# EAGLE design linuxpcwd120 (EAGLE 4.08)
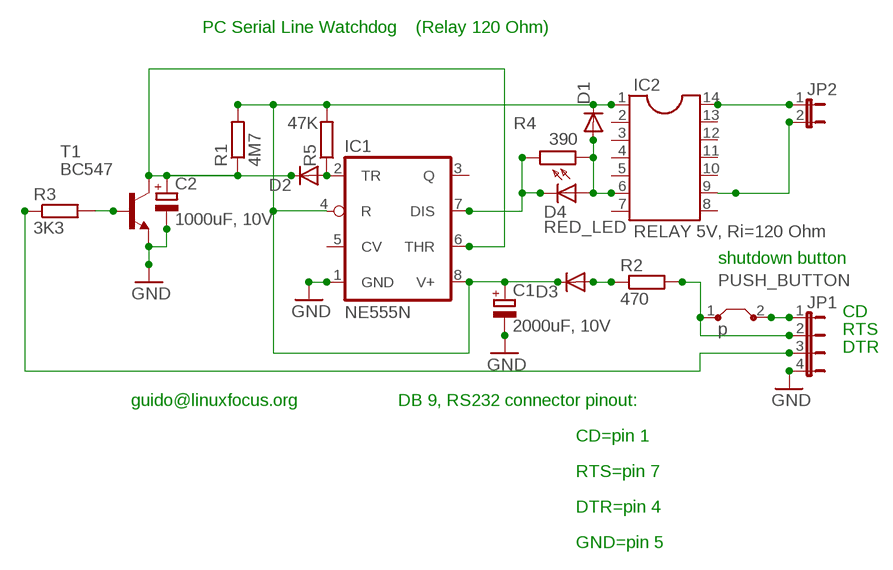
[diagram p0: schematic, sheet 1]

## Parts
C1  2000uF, 10V  CPOL-EUE3.5-10  [E3,5-10]
C2  1000uF, 10V  CPOL-EUE3.5-10  [E3,5-10]
D1  DIODE-D-5  [D-5]
D2  DIODE-D-7.5  [D-7.5]
D3  DIODE-D-5  [D-5]
D4  RED_LED  LED3MM  [LED3MM]
IC1  NE555N  [DIL08]
IC2  RELAY 5V, Ri=120 Ohm  DIL14  [DIL14]
JP1  JP4E  [JP4]
JP2  JP1E  [JP1]
PUSH_BUTTON  p  J5MM  [05]
R1  4M7  R-EU_0204/5  [0204/5]
R2  470  R-EU_0204/5  [0204/5]
R3  3K3  R-EU_0204/5  [0204/5]
R4  390  R-EU_0204/5  [0204/5]
R5  47K  R-EU_0204/7  [0204/7]
T1  BC547  [TO92]

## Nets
GND: C1.- C2.- IC1.1(GND) JP1.4 T1.1(E)
N$2: D2.A IC1.2(TR) R5.1
N$3: C2.+ D2.C IC1.6(THR) R1.1 T1.3(C)
N$5: R3.2 T1.2(B)
N$6: D3.A R2.1
N$8: IC2.14 JP2.1
N$9: D1.A D4.A IC2.6 R4.2
N$11: D4.K(C) IC1.7(DIS) R4.1
N$12: IC2.9 JP2.2
N$13: JP1.1 PUSH_BUTTON.2
N$14: JP1.2 PUSH_BUTTON.1 R2.2
N$15: JP1.3 R3.1
V+: C1.+ D1.C D3.C IC1.4(R) IC1.8(V+) IC2.1 R1.2 R5.2
Unconnected: IC1.3(Q) IC1.5(CV) IC2.2 IC2.3 IC2.4 IC2.5 IC2.7 IC2.8 IC2.10 IC2.11 IC2.12 IC2.13

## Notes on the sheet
- PC Serial Line Watchdog | (Relay 120 Ohm)
- shutdown button
- CD
- RTS
- DTR
- guido@linuxfocus.org | DB 9, RS232 connector pinout:
- CD=pin 1
- RTS=pin 7
- DTR=pin 4
- GND=pin 5

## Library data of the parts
C1 C2 = rclgus:CPOL-EU: POLARIZED CAPACITOR, European symbol
D1-D3 = diode:DIODE-: DIODE
D4 = led:LED3MM: LED
IC1 = linear:*555: TIMER
IC2 = dil:DIL14: SOCKET Dual In Line
JP1 = jumper:JP4E: JUMPER
JP2 = jumper:JP1E: JUMPER
PUSH_BUTTON = jumper:J: Bridge
R1-R5 = rclgus:R-EU_: RESISTOR, European symbol
T1 = transistor-npn:BC547: NPN TRANSISTOR

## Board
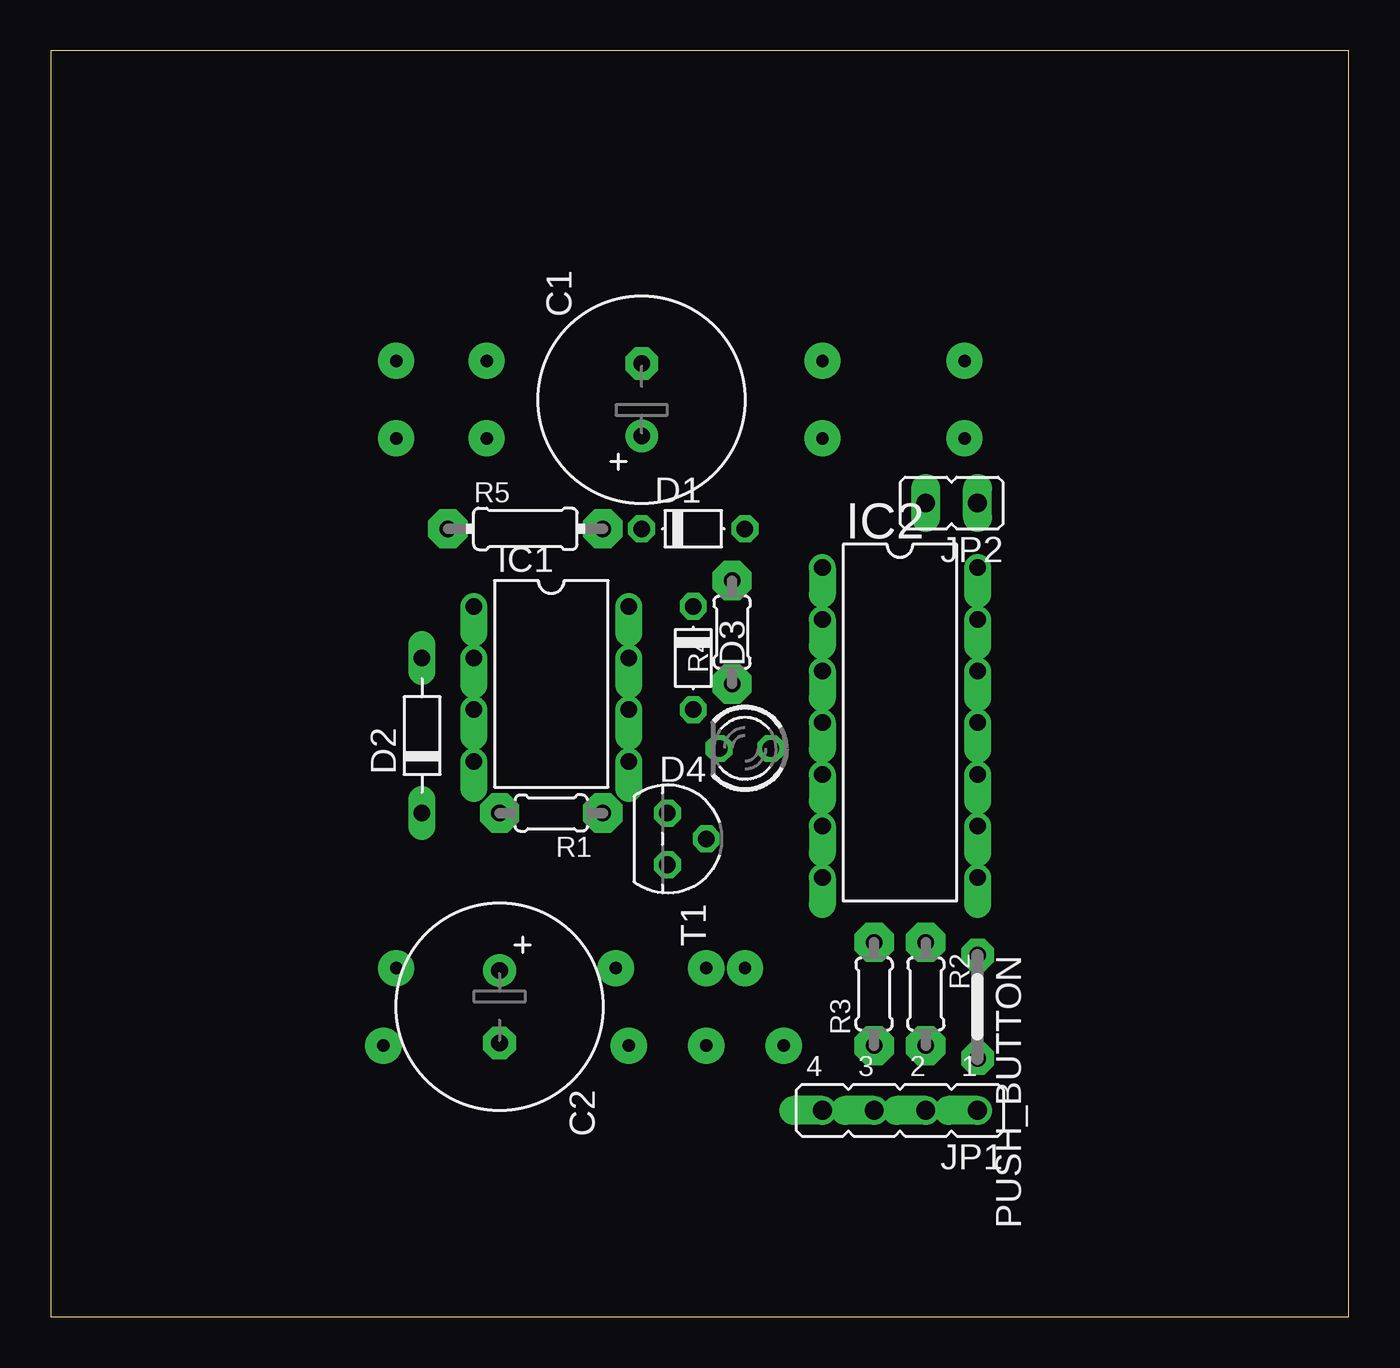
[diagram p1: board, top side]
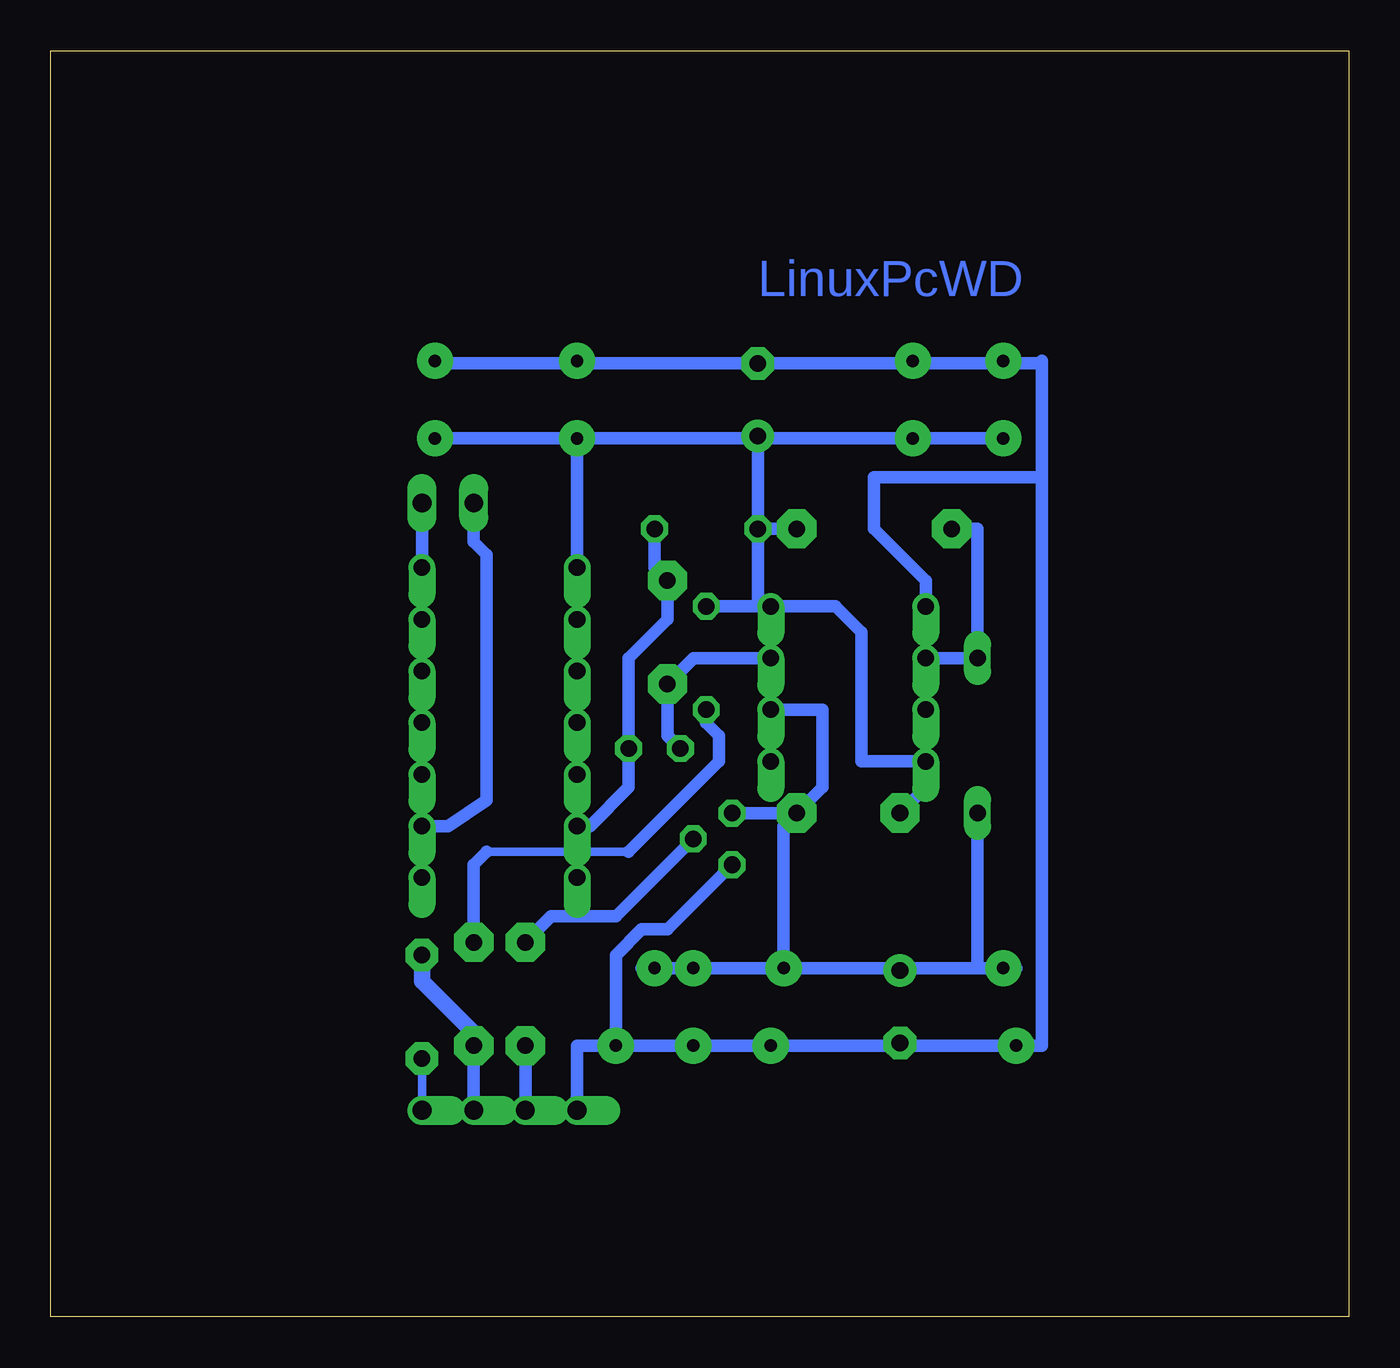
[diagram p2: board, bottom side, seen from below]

Size 63.8 x 62.22 mm. Coordinates in mm from the lower left corner, seen from the top.
Outline: 0,0 63.8,0 63.8,62.22 0,62.22 0,0
Copper layers used: Top, Bottom

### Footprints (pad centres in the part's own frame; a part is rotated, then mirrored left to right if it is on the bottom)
E3,5-10 = drill 0.813 pad 1.6 round: + -1.778,0 | drill 0.813 pad 1.6 octagon: - 1.778,0
D-5 = drill 0.813 octagon: A 2.54,0; C -2.54,0
D-7.5 = drill 0.813 long: A 3.81,0; C -3.81,0
LED3MM = drill 0.813 octagon: A -1.27,0; K 1.27,0
DIL08 = drill 0.813 offset: 1 -3.81,-3.81; 2 -1.27,-3.81; 3 1.27,-3.81; 4 3.81,-3.81; 5 3.81,3.81; 6 1.27,3.81; 7 -1.27,3.81; 8 -3.81,3.81
DIL14 = drill 0.813 offset: 1 -7.62,-3.81; 2 -5.08,-3.81; 3 -2.54,-3.81; 4 0,-3.81; 5 2.54,-3.81; 6 5.08,-3.81; 7 7.62,-3.81; 8 7.62,3.81; 9 5.08,3.81; 10 2.54,3.81; 11 0,3.81; 12 -2.54,3.81; 13 -5.08,3.81; 14 -7.62,3.81
JP4 = drill 0.914 offset: 1 -3.81,0; 2 -1.27,0; 3 1.27,0; 4 3.81,0
JP1 = drill 0.914 long: 1 0,-1.27; 2 0,1.27
05 = drill 0.813 pad 1.6 octagon: 1 -2.54,0; 2 2.54,0
0204/5 = drill 0.813 pad 1.93 octagon: 1 -2.54,0; 2 2.54,0
0204/7 = drill 0.813 pad 1.93 octagon: 1 -3.81,0; 2 3.81,0
TO92 = drill 0.813 octagon: 1 1.27,0; 2 0,1.905; 3 -1.27,0

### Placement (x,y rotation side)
C1  29.05,45.08 90 top
C2  22.06,15.23 270 top
D1  31.59,38.73 0 top
D2  18.25,28.57 90 top
D3  31.59,32.38 270 top
D4  34.12,27.94 180 top
IC1  24.6,31.11 270 top
IC2  41.75,29.2 270 top
JP1  41.75,10.16 180 top
JP2  44.29,40 90 top
PUSH_BUTTON  45.55,15.23 270 top
R1  24.6,24.76 180 top
R2  43.02,15.87 270 top
R3  40.48,15.87 90 top
R4  33.49,33.65 90 top
R5  23.33,38.73 0 top
T1  30.32,23.49 270 top

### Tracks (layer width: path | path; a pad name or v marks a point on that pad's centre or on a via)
GND  (via drill 0.61 pad 1.78)
  Bottom 0.254: 21.43,13.33 C2.- | 21.43,13.33
  Bottom 0.61: 15.2,46.86 C1.- | 15.2,46.86 15.08,46.98 15.08,41.27 | 15.08,41.27 15.08,13.33 v16.34,13.33 21.43,13.33 v28.41,13.33 v32.22,13.33 v36.03,13.33 | v36.03,13.33 37.94,13.33 JP1.4 | 15.2,46.86 44.79,46.86 v44.92,46.98 | IC1.1 20.79,36.19 23.33,38.73 23.33,41.27 15.08,41.27 | T1.1 33.49,19.04 34.76,19.04 36.03,17.77 v36.03,13.33
N$1  (via drill 0.61 pad 1.78)
  other vias: 16.98,46.98
N$2
  Bottom 0.61: IC1.2 D2.A 18.25,38.73 R5.1
N$3  (via drill 0.61 pad 1.78)
  Bottom 0.254: 21.43,17.14 C2.+ | 21.43,17.14
  Bottom 0.61: R1.1 T1.3 | IC1.6 25.87,29.84 25.87,26.03 R1.1 | 18.25,17.14 D2.C | 18.25,17.14 v16.98,17.14 16.34,17.14 | 18.25,17.14 21.43,17.14 v27.77,17.14 | v27.77,17.14 v32.22,17.14 v34.12,17.14 34.76,17.14 | v27.77,17.14 27.77,24.12 R1.1
N$4  (via drill 0.61 pad 1.78)
  other vias: 37.94,46.98
N$5
  Bottom 0.61: T1.2 36.03,19.68 39.21,19.68 R3.2
N$6
  Bottom 0.406: 35.4,22.85 42.38,22.85
  Bottom 0.61: D3.A 31.59,29.2 30.95,28.57 30.95,27.3 35.4,22.85 | 43.02,19.68 R2.1 43.02,22.22 42.38,22.85
N$7  (via drill 0.61 pad 1.78)
  other vias: 21.43,46.98
N$8
  Bottom 0.61: IC2.14 JP2.1
N$9
  Bottom 0.61: D1.A 34.12,36.83 R4.2 33.49,34.28 35.4,32.38 D4.A 35.4,26.03 37.3,24.12 IC2.6
N$11
  Bottom 0.61: D4.K 33.49,28.57 R4.1 32.22,32.38 IC1.7
N$12
  Bottom 0.61: JP2.2 43.02,38.09 42.38,37.46 42.38,25.4 44.29,24.12 IC2.9
N$13
  Bottom 0.406: JP1.1 PUSH_BUTTON.2
N$14  (via drill 0.61 pad 1.78)
  Top 0.254: R2.2
  Bottom 0.61: JP1.2 R2.2
  Bottom 0.813: R2.2 43.02,13.96 45.55,16.5 PUSH_BUTTON.1
  other vias: 43.01,13.33
N$15
  Bottom 0.61: JP1.3 R3.1
V+  (via drill 0.61 pad 1.78)
  Bottom 0.61: D1.C R5.2 | 29.05,34.92 IC1.8 25.23,34.92 23.97,33.65 23.97,27.3 IC1.4 20.79,26.03 R1.2 | 29.05,34.92 D1.C | 29.05,34.92 D3.C | 29.05,43.17 C1.+ | D1.C 29.05,43.17 | v37.94,43.17 IC2.1 | 29.05,43.17 v21.43,43.17 v16.98,43.17 | v37.94,43.17 v44.92,43.17 | 29.05,43.17 v37.94,43.17

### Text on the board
Bottom: LinuxPcWD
